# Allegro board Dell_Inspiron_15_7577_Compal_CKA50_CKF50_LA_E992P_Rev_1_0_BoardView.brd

Outline 383.3 x 146.9 mm; copper layers: TOP, GND1, IN1, GND2, IN2, VCC, IN3, IN4, GND3, IN5, GND4, BOTTOM. Coordinates in mm from the lower left corner of the outline.

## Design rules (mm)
constraint set DEFAULT: min track width 0.14
net group 18/15: nets H_THERMTRIP# H_THERMTRIP#_R
net group ASYNCHRONOUS: nets H_PROCHOT# PROCHOT
net group CLK_PCIE_N5: nets CLK_PCIE_N5 CLK_PCIE_P5
net group CPU_DDI3_N0: nets CPU_DDI3_N0 CPU_DDI3_P0
net group CPU_DDI3_N1: nets CPU_DDI3_N1 CPU_DDI3_P1
net group CRT: nets CRT_DDCCLK_CON CRT_DDCDATA_CON
net group DDC_SCL_HDMI: nets DDC_SCL_HDMI DDC_SDA_HDMI
net group DDI3_AUXN: nets DDI3_AUXN DDI3_AUXP
net group DDI3_AUXN_C: nets DDI3_AUXN_C DDI3_AUXP_C
net group DDR_A_CLK0: nets DDR_A_CLK0 DDR_A_CLK#0
net group DDR_A_CLK1: nets DDR_A_CLK1 DDR_A_CLK#1
net group DDR_ALERT: nets DDR_A_ALERT# DDR_B_ALERT#
net group DDR_B_CLK0: nets DDR_B_CLK0 DDR_B_CLK#0
net group DDR_B_CLK1: nets DDR_B_CLK1 DDR_B_CLK#1
net group DDR_RESET: nets DDR4_DRAMRST# H_DRAMRST#
net group DIFFPAIR1: nets CLK_SMB DAT_SMB
net group DMIC_CLK: nets DMIC_CLK DMIC_DAT
net group DMIC_CLK_R: nets DMIC_CLK_R DMIC_DATA_R
net group DP6: nets ISUMN_SA ISUMP_SA
net group DP_N0: nets DP_N0 DP_P0
net group DP_N1: nets DP_N1 DP_P1
net group IFPC_CLK_CN: nets IFPC_CLK_CN IFPC_CLK_CP
net group IFPC_CLK_N: nets IFPC_CLK_N IFPC_CLK_P
net group IFPC_TX0_CN: nets IFPC_TX0_CN IFPC_TX0_CP
net group IFPC_TX0_N: nets IFPC_TX0_N IFPC_TX0_P
net group IFPC_TX1_CN: nets IFPC_TX1_CN IFPC_TX1_CP
net group IFPC_TX1_N: nets IFPC_TX1_N IFPC_TX1_P
net group IFPC_TX2_CN: nets IFPC_TX2_CN IFPC_TX2_CP
net group IFPC_TX2_N: nets IFPC_TX2_N IFPC_TX2_P
net group PCIE_PRX_TBTTX_N1: nets PCIE_PRX_TBTTX_N1 PCIE_PRX_TBTTX_P1
net group PCIE_PRX_TBTTX_N1_C: nets PCIE_PRX_TBTTX_N1_C PCIE_PRX_TBTTX_P1_C
net group PCIE_PRX_TBTTX_N2: nets PCIE_PRX_TBTTX_N2 PCIE_PRX_TBTTX_P2
net group PCIE_PRX_TBTTX_N2_C: nets PCIE_PRX_TBTTX_N2_C PCIE_PRX_TBTTX_P2_C
net group PCIE_PRX_TBTTX_N3: nets PCIE_PRX_TBTTX_N3 PCIE_PRX_TBTTX_P3
net group PCIE_PRX_TBTTX_N3_C: nets PCIE_PRX_TBTTX_N3_C PCIE_PRX_TBTTX_P3_C
net group PCIE_PRX_TBTTX_N4: nets PCIE_PRX_TBTTX_N4 PCIE_PRX_TBTTX_P4
net group PCIE_PRX_TBTTX_N4_C: nets PCIE_PRX_TBTTX_N4_C PCIE_PRX_TBTTX_P4_C
net group PCIE_PTX_LANRX_N5: nets PCIE_PTX_LANRX_N5 PCIE_PTX_LANRX_N5_C
net group PCIE_PTX_LANRX_P5: nets PCIE_PTX_LANRX_P5 PCIE_PTX_LANRX_P5_C
net group PCIE_PTX_TBTRX_N1: nets PCIE_PTX_TBTRX_N1 PCIE_PTX_TBTRX_P1
net group PCIE_PTX_TBTRX_N1_C: nets PCIE_PTX_TBTRX_N1_C PCIE_PTX_TBTRX_P1_C
net group PCIE_PTX_TBTRX_N2: nets PCIE_PTX_TBTRX_N2 PCIE_PTX_TBTRX_P2
net group PCIE_PTX_TBTRX_N2_C: nets PCIE_PTX_TBTRX_N2_C PCIE_PTX_TBTRX_P2_C
net group PCIE_PTX_TBTRX_N3: nets PCIE_PTX_TBTRX_N3 PCIE_PTX_TBTRX_P3
net group PCIE_PTX_TBTRX_N3_C: nets PCIE_PTX_TBTRX_N3_C PCIE_PTX_TBTRX_P3_C
net group PCIE_PTX_TBTRX_N4: nets PCIE_PTX_TBTRX_N4 PCIE_PTX_TBTRX_P4
net group PCIE_PTX_TBTRX_N4_C: nets PCIE_PTX_TBTRX_N4_C PCIE_PTX_TBTRX_P4_C
net group PLATFORM_RESET: nets TBT_RESET_N_EC# USB_EN#
net group TBT_A_AUX_N: nets TBT_A_AUX_N TBT_A_AUX_P
net group TBT_A_AUX_N_C: nets TBT_A_AUX_N_C TBT_A_AUX_P_C
net group TBT_A_USB20_L_NB: nets TBT_A_USB20_L_NB TBT_A_USB20_L_PB
net group TBT_A_USB20_L_NT: nets TBT_A_USB20_L_NT TBT_A_USB20_L_PT
net group TBT_A_USB20_N: nets TBT_A_USB20_N TBT_A_USB20_P
net group TBT_A_USB20_NB: nets TBT_A_USB20_NB TBT_A_USB20_PB
net group TBT_A_USB20_NT: nets TBT_A_USB20_NT TBT_A_USB20_PT
net group TBTA_SBU: nets TBTA_SBU1 TBTA_SBU2
net group TMDS_T_TX0N_R: nets TMDS_T_TX0N_R TMDS_T_TX0P_R
net group TMDS_T_TX1N_R: nets TMDS_T_TX1N_R TMDS_T_TX1P_R
net group TMDS_T_TX2N_R: nets TMDS_T_TX2N_R TMDS_T_TX2P_R
net group TMDS_T_TXCN_R: nets TMDS_T_TXCN_R TMDS_T_TXCP_R
net group UP2: nets +1.2V_RTM N10178
net group USB3_A_TTX_DRX_N0: nets USB3_A_TTX_DRX_N0 USB3_A_TTX_DRX_P0
net group USB3_A_TTX_DRX_N1: nets USB3_A_TTX_DRX_N1 USB3_A_TTX_DRX_P1
net group USB3RN1_C: nets USB3RN1_C USB3RP1_C
net group USB3RN1_RE: nets USB3RN1_RE USB3RP1_RE
net group USB3TN1_C: nets USB3TN1_C USB3TP1_C
net group USB3TN1_RE: nets USB3TN1_RE USB3TP1_RE
net group USB3TN1_RE_C: nets USB3TN1_RE_C USB3TP1_RE_C
net group USB3TN2_C: nets USB3TN2_C USB3TP2_C
net group USB3TN3_C: nets USB3TN3_C USB3TP3_C
net group USB20_N2_L: nets USB20_N2_L USB20_P2_L
net group USB20_N3_L: nets USB20_N3_L USB20_P3_L
net group USB20_N8: nets USB20_N8 USB20_P8
net group USB20_N8_R: nets USB20_N8_R USB20_P8_R
net group 5: nets KSI0 KSI1 KSI2 KSI3 KSI4 KSI5 KSI6 KSI7 KSO0 KSO1 KSO2 KSO3 KSO4 KSO5 KSO6 KSO7 KSO8 KSO9 KSO10 KSO11 KSO12 KSO13 KSO14 KSO15 KSO16
net group 10: nets AUD_HP1_JACK_L AUD_HP1_JACK_L1 AUD_HP1_JACK_R AUD_HP1_JACK_R1 AUD_PORTA_L_R_B AUD_PORTA_R_R_B AUD_SPK_L+ AUD_SPK_L+_C AUD_SPK_L- AUD_SPK_L-_C AUD_SPK_R+ AUD_SPK_R+_C AUD_SPK_R- AUD_SPK_R-_C BAT1_LED# BAT2_LED# BREATH_LED# BREATH_LED_MB BREATH_LED_R2 CAP_LED CAP_LED_R KB_BL_DET KB_LED_PWM KB_LED_PWM# LED1 LED2 LINE1_VREFO_L LINE1_VREFO_R MIC2_VREFO PCH_SATA_LED# REMOTE1+ REMOTE1- REMOTE2+ REMOTE2- SATA_LED_EN SSD_LED#
net group 12: nets ALL_SYS_PWRGD CPU_TRIGGER CPU_TRIGGER_R H_CATERR# H_CPUPWRGD H_PM_DOWN H_PM_DOWN_R H_PM_SYNC_R H_PROCHOT#_R H_VCCST_PWRGD PCH_PLTRST# PCH_PLTRST#_EC PCH_TRIGGER PCH_TRIGGER_R PLTRST_CPU# RUNPWROK TBT_RST#_R VCCST_PWRGD_CPU XDP_PLTRST# XDP_PWRGOOD
net group 12/15: nets SD_CLK SD_CLK_R SD_CMD SD_D0 SD_D1 SD_D2 SD_D3
net group 15: nets AC_PRESENT ACAV_IN MEC_XTAL1 MEC_XTAL1_R MEC_XTAL2 PCH_DPWROK PCH_RSMRST# PCH_RSMRST#_R PCH_RTCRST# PCH_RTCX1 PCH_RTCX2 PCH_SRTCRST# RESET_N SUSCLK SUSCLK_R SYS_RESET# TBT_RESET_N TBT_XTAL_25_IN TBT_XTAL_25_IN_R TBT_XTAL_25_OUT TBT_XTAL_25_OUT_R TBTA_MRESET XDP_DBRESET# XTLI XTLO
net group 15/12: nets VR_SVID_ALERT# VR_SVID_ALERT#_R VR_SVID_CLK VR_SVID_DATA
net group 18/12: nets H_PECI PECI PECI_EC PECI_EC_R
net group 25: nets USB2_VBUSSENSE VCCIO_SENSE VSSIO_SENSE
net group AUDIO: nets LINE1-L_C LINE1-L_R LINE1_L LINE1_R
net group DDRCMD_4/12_16: nets DDR_A_ACT# DDR_A_BG0 DDR_A_BG1 DDR_A_BS0 DDR_A_BS1 DDR_A_CAS# DDR_A_CKE0 DDR_A_CKE1 DDR_A_CS#0 DDR_A_CS#1 DDR_A_MA0 DDR_A_MA1 DDR_A_MA2 DDR_A_MA3 DDR_A_MA4 DDR_A_MA5 DDR_A_MA6 DDR_A_MA7 DDR_A_MA8 DDR_A_MA9 DDR_A_MA10 DDR_A_MA11 DDR_A_MA12 DDR_A_MA13 DDR_A_ODT0 DDR_A_ODT1 DDR_A_PAR DDR_A_RAS# DDR_A_WE# DDR_B_ACT# DDR_B_BG0 DDR_B_BG1 DDR_B_BS0 DDR_B_BS1 DDR_B_CAS# DDR_B_CKE0 DDR_B_CKE1 DDR_B_CS#0 DDR_B_CS#1 DDR_B_MA0 DDR_B_MA1 DDR_B_MA2 DDR_B_MA3 DDR_B_MA4 DDR_B_MA5 DDR_B_MA6 DDR_B_MA7 DDR_B_MA8 DDR_B_MA9 DDR_B_MA10 DDR_B_MA11 DDR_B_MA12 DDR_B_MA13 DDR_B_ODT0 DDR_B_ODT1 DDR_B_PAR DDR_B_RAS# DDR_B_WE#
net group DDRD0_4/8_25: nets DDR_A_D0 DDR_A_D1 DDR_A_D2 DDR_A_D3 DDR_A_D4 DDR_A_D5 DDR_A_D6 DDR_A_D7 DDR_A_D16 DDR_A_D17 DDR_A_D18 DDR_A_D19 DDR_A_D20 DDR_A_D21 DDR_A_D22 DDR_A_D23 DDR_A_D32 DDR_A_D33 DDR_A_D34 DDR_A_D35 DDR_A_D36 DDR_A_D37 DDR_A_D38 DDR_A_D39 DDR_A_D48 DDR_A_D49 DDR_A_D50 DDR_A_D51 DDR_A_D52 DDR_A_D53 DDR_A_D54 DDR_A_D55 DDR_B_D0 DDR_B_D1 DDR_B_D2 DDR_B_D3 DDR_B_D4 DDR_B_D5 DDR_B_D6 DDR_B_D7 DDR_B_D16 DDR_B_D17 DDR_B_D18 DDR_B_D19 DDR_B_D20 DDR_B_D21 DDR_B_D22 DDR_B_D23 DDR_B_D32 DDR_B_D33 DDR_B_D34 DDR_B_D35 DDR_B_D36 DDR_B_D37 DDR_B_D38 DDR_B_D39 DDR_B_D48 DDR_B_D49 DDR_B_D50 DDR_B_D51 DDR_B_D52 DDR_B_D53 DDR_B_D54 DDR_B_D55
net group DDRD1_4/8_25: nets DDR_A_D8 DDR_A_D9 DDR_A_D10 DDR_A_D11 DDR_A_D12 DDR_A_D13 DDR_A_D14 DDR_A_D15 DDR_A_D24 DDR_A_D25 DDR_A_D26 DDR_A_D27 DDR_A_D28 DDR_A_D29 DDR_A_D30 DDR_A_D31 DDR_A_D40 DDR_A_D41 DDR_A_D42 DDR_A_D43 DDR_A_D44 DDR_A_D45 DDR_A_D46 DDR_A_D47 DDR_A_D56 DDR_A_D57 DDR_A_D58 DDR_A_D59 DDR_A_D60 DDR_A_D61 DDR_A_D62 DDR_A_D63 DDR_B_D8 DDR_B_D9 DDR_B_D10 DDR_B_D11 DDR_B_D12 DDR_B_D13 DDR_B_D14 DDR_B_D15 DDR_B_D24 DDR_B_D25 DDR_B_D26 DDR_B_D27 DDR_B_D28 DDR_B_D29 DDR_B_D30 DDR_B_D31 DDR_B_D40 DDR_B_D41 DDR_B_D42 DDR_B_D43 DDR_B_D44 DDR_B_D45 DDR_B_D46 DDR_B_D47 DDR_B_D56 DDR_B_D57 DDR_B_D58 DDR_B_D59 DDR_B_D60 DDR_B_D61 DDR_B_D62 DDR_B_D63
net group DDRDQS_25: nets DDR_A_DQS0 DDR_A_DQS1 DDR_A_DQS2 DDR_A_DQS3 DDR_A_DQS4 DDR_A_DQS5 DDR_A_DQS6 DDR_A_DQS7 DDR_A_DQS#0 DDR_A_DQS#1 DDR_A_DQS#2 DDR_A_DQS#3 DDR_A_DQS#4 DDR_A_DQS#5 DDR_A_DQS#6 DDR_A_DQS#7 DDR_B_DQS0 DDR_B_DQS1 DDR_B_DQS2 DDR_B_DQS3 DDR_B_DQS4 DDR_B_DQS5 DDR_B_DQS6 DDR_B_DQS7 DDR_B_DQS#0 DDR_B_DQS#1 DDR_B_DQS#2 DDR_B_DQS#3 DDR_B_DQS#4 DDR_B_DQS#5 DDR_B_DQS#6 DDR_B_DQS#7
net group DMI: nets DMI_CRX_PTX_N0 DMI_CRX_PTX_N1 DMI_CRX_PTX_N2 DMI_CRX_PTX_N3 DMI_CRX_PTX_P0 DMI_CRX_PTX_P1 DMI_CRX_PTX_P2 DMI_CRX_PTX_P3 DMI_CTX_PRX_N0 DMI_CTX_PRX_N1 DMI_CTX_PRX_N2 DMI_CTX_PRX_N3 DMI_CTX_PRX_P0 DMI_CTX_PRX_P1 DMI_CTX_PRX_P2 DMI_CTX_PRX_P3
net group DP_12_15: nets CRT_B CRT_G CRT_HSYNC_CON CRT_R CRT_VSYNC_CON DP_CRT_B DP_CRT_G DP_CRT_HSYNC_CON DP_CRT_R DP_CRT_VSYNC_CON
net group EDP_12_15: nets EDP_AUXN EDP_AUXN_C EDP_AUXP EDP_AUXP_C EDP_TXN0 EDP_TXN0_C EDP_TXN1 EDP_TXN1_C EDP_TXN2 EDP_TXN2_C EDP_TXN3 EDP_TXN3_C EDP_TXP0 EDP_TXP0_C EDP_TXP1 EDP_TXP1_C EDP_TXP2 EDP_TXP2_C EDP_TXP3 EDP_TXP3_C
net group ESPI_5_15: nets ESPI_CLK ESPI_CS# ESPI_IO0 ESPI_IO1 ESPI_IO2 ESPI_IO3 ESPI_RESET# PCH_ESPI_CLK PCH_ESPI_IO0 PCH_ESPI_IO1 PCH_ESPI_IO2 PCH_ESPI_IO3
net group FBA_DBI: nets FBA_DBI0 FBA_DBI1 FBA_DBI2 FBA_DBI3 FBA_DBI4 FBA_DBI5 FBA_DBI6 FBA_DBI7
net group GDDR5_CLK_13.5/12_20: nets FBB_CLK0 FBB_CLK0# FBB_CLK1 FBB_CLK1#
net group GDDR5_CMD_13.5/12_20: nets FBA_CMD0 FBA_CMD1 FBA_CMD2 FBA_CMD3 FBA_CMD4 FBA_CMD5 FBA_CMD6 FBA_CMD7 FBA_CMD8 FBA_CMD9 FBA_CMD10 FBA_CMD11 FBA_CMD12 FBA_CMD13 FBA_CMD14 FBA_CMD15 FBA_CMD16 FBA_CMD17 FBA_CMD18 FBA_CMD19 FBA_CMD20 FBA_CMD21 FBA_CMD22 FBA_CMD23 FBA_CMD24 FBA_CMD25 FBA_CMD26 FBA_CMD27 FBA_CMD28 FBA_CMD29 FBA_CMD30 FBA_CMD31 FBB_CMD0 FBB_CMD1 FBB_CMD2 FBB_CMD3 FBB_CMD4 FBB_CMD5 FBB_CMD6 FBB_CMD7 FBB_CMD8 FBB_CMD9 FBB_CMD10 FBB_CMD11 FBB_CMD12 FBB_CMD13 FBB_CMD14 FBB_CMD15 FBB_CMD16 FBB_CMD17 FBB_CMD18 FBB_CMD19 FBB_CMD20 FBB_CMD21 FBB_CMD22 FBB_CMD23 FBB_CMD24 FBB_CMD25 FBB_CMD26 FBB_CMD27 FBB_CMD28 FBB_CMD29 FBB_CMD30 FBB_CMD31 FBC_CMD0 FBC_CMD1 FBC_CMD2 FBC_CMD3 FBC_CMD4 FBC_CMD5 FBC_CMD6 FBC_CMD7 FBC_CMD8 FBC_CMD9 FBC_CMD10 FBC_CMD11 FBC_CMD12 FBC_CMD13 FBC_CMD14 FBC_CMD15 FBC_CMD16 FBC_CMD17 FBC_CMD18 FBC_CMD19 FBC_CMD20 FBC_CMD21 FBC_CMD22 FBC_CMD23 FBC_CMD24 FBC_CMD25 FBC_CMD26 FBC_CMD27 FBC_CMD28 FBC_CMD29 FBC_CMD30 FBC_CMD31
net group GDDR5_DATA/DBI/EDC_13.5/16/18_20: nets FBB_D0 FBB_D1 FBB_D2 FBB_D3 FBB_D4 FBB_D5 FBB_D6 FBB_D7 FBB_D8 FBB_D9 FBB_D10 FBB_D11 FBB_D12 FBB_D13 FBB_D14 FBB_D15 FBB_D16 FBB_D17 FBB_D18 FBB_D19 FBB_D20 FBB_D21 FBB_D22 FBB_D23 FBB_D24 FBB_D25 FBB_D26 FBB_D27 FBB_D28 FBB_D29 FBB_D30 FBB_D31 FBB_D32 FBB_D33 FBB_D34 FBB_D35 FBB_D36 FBB_D37 FBB_D38 FBB_D39 FBB_D40 FBB_D41 FBB_D42 FBB_D43 FBB_D44 FBB_D45 FBB_D46 FBB_D47 FBB_D48 FBB_D49 FBB_D50 FBB_D51 FBB_D52 FBB_D53 FBB_D54 FBB_D55 FBB_D56 FBB_D57 FBB_D58 FBB_D59 FBB_D60 FBB_D61 FBB_D62 FBB_D63 FBB_DBI0 FBB_DBI1 FBB_DBI2 FBB_DBI3 FBB_DBI4 FBB_DBI5 FBB_DBI6 FBB_DBI7 FBB_EDC0 FBB_EDC1 FBB_EDC2 FBB_EDC3 FBB_EDC4 FBB_EDC5 FBB_EDC6 FBB_EDC7 FBC_DBI0 FBC_DBI1 FBC_DBI2 FBC_DBI3 FBC_DBI4 FBC_DBI5 FBC_DBI6 FBC_DBI7
net group GDDR5_WCLK_10.8/16/18_20: nets FBA_WCK01 FBA_WCK01# FBA_WCK23 FBA_WCK23# FBA_WCK45 FBA_WCK45# FBA_WCK67 FBA_WCK67# FBB_WCK01 FBB_WCK01# FBB_WCK23 FBB_WCK23# FBB_WCK45 FBB_WCK45# FBB_WCK67 FBB_WCK67# FBC_WCK01 FBC_WCK01# FBC_WCK23 FBC_WCK23# FBC_WCK45 FBC_WCK45# FBC_WCK67 FBC_WCK67#
net group GND: nets AUD_AGND
net group HDA: nets HDA_BITCLK_AUDIO
net group HDA_5_15: nets AUD_AZA_CPU_SCLK AUD_AZA_CPU_SCLK_R AUD_AZA_CPU_SDI AUD_AZA_CPU_SDI_R AUD_AZA_CPU_SDO AUD_AZA_CPU_SDO_R HDA_BITCLK HDA_CODEC_SDIN0 HDA_SDIN0_AUDIO HDA_SDOUT HDA_SDOUT_AUDIO HDA_SYNC HDA_SYNC_AUDIO
net group HDMI: nets IFPC_I2C_8409_CLK IFPC_I2C_8409_DAT IFPC_I2C_CLK IFPC_I2C_CLK_R IFPC_I2C_DAT IFPC_I2C_DAT_R
net group HDMI_12_20: nets TMDS_T_TX0N TMDS_T_TX0P TMDS_T_TX1N TMDS_T_TX1P TMDS_T_TX2N TMDS_T_TX2P TMDS_T_TXCN TMDS_T_TXCP
net group I2C_5_15: nets CLK_TP_SIO DAT_TP_SIO I2C1_SCK_TP I2C1_SCK_TP_C I2C1_SDA_TP I2C1_SDA_TP_C
net group LAN_30: nets MDI0+ MDI0- MDI1+ MDI1- MDI2+ MDI2- MDI3+ MDI3- MDO0+ MDO0- MDO1+ MDO1- MDO2+ MDO2- MDO3+ MDO3-
net group LED: nets MASK_SATA_LED#
net group PCIE_12: nets PCIE_PRX_SSDTX_N10 PCIE_PRX_SSDTX_N11 PCIE_PRX_SSDTX_N12 PCIE_PRX_SSDTX_P10 PCIE_PRX_SSDTX_P11 PCIE_PRX_SSDTX_P12 PCIE_PRX_WLANTX_N6 PCIE_PRX_WLANTX_P6 PCIE_PTX_SSDRX_N10 PCIE_PTX_SSDRX_N10_C PCIE_PTX_SSDRX_N11 PCIE_PTX_SSDRX_N11_C PCIE_PTX_SSDRX_N12 PCIE_PTX_SSDRX_N12_C PCIE_PTX_SSDRX_P10 PCIE_PTX_SSDRX_P10_C PCIE_PTX_SSDRX_P11 PCIE_PTX_SSDRX_P11_C PCIE_PTX_SSDRX_P12 PCIE_PTX_SSDRX_P12_C PCIE_PTX_WLANRX_N6 PCIE_PTX_WLANRX_P6 PCIE_PTX_WLANRX_RE_N6 PCIE_PTX_WLANRX_RE_P6 SATA_PRX_SSDTX_N0A SATA_PRX_SSDTX_P0A SATA_PTX_SSDRX_N0A SATA_PTX_SSDRX_N0A_C SATA_PTX_SSDRX_P0A SATA_PTX_SSDRX_P0A_C
net group PCIE_LAN: nets PCIE_PRX_LANTX_N5 PCIE_PRX_LANTX_N5_C PCIE_PRX_LANTX_P5 PCIE_PRX_LANTX_P5_C
net group PCIE_WLAN: nets CPU_DDI1_N0 CPU_DDI1_N1 CPU_DDI1_N2 CPU_DDI1_N3 CPU_DDI1_P0 CPU_DDI1_P1 CPU_DDI1_P2 CPU_DDI1_P3 CPU_DDI2_N0 CPU_DDI2_N1 CPU_DDI2_N2 CPU_DDI2_N3 CPU_DDI2_P0 CPU_DDI2_P1 CPU_DDI2_P2 CPU_DDI2_P3 CPU_DP1_AUXN_C CPU_DP1_AUXP_C CPU_DP1_N0_C CPU_DP1_N1_C CPU_DP1_N2_C CPU_DP1_N3_C CPU_DP1_P0_C CPU_DP1_P1_C CPU_DP1_P2_C CPU_DP1_P3_C CPU_DP2_AUXN_C CPU_DP2_AUXP_C CPU_DP2_N0_C CPU_DP2_N1_C CPU_DP2_N2_C CPU_DP2_N3_C CPU_DP2_P0_C CPU_DP2_P1_C CPU_DP2_P2_C CPU_DP2_P3_C DDI1_AUXN DDI1_AUXP DDI2_AUXN DDI2_AUXP
net group PEG_12_15: nets PEG_GTX_C_HRX_N0 PEG_GTX_C_HRX_N1 PEG_GTX_C_HRX_N2 PEG_GTX_C_HRX_N3 PEG_GTX_C_HRX_N4 PEG_GTX_C_HRX_N5 PEG_GTX_C_HRX_N6 PEG_GTX_C_HRX_N7 PEG_GTX_C_HRX_N8 PEG_GTX_C_HRX_N9 PEG_GTX_C_HRX_N10 PEG_GTX_C_HRX_N11 PEG_GTX_C_HRX_N12 PEG_GTX_C_HRX_N13 PEG_GTX_C_HRX_N14 PEG_GTX_C_HRX_N15 PEG_GTX_C_HRX_P0 PEG_GTX_C_HRX_P1 PEG_GTX_C_HRX_P2 PEG_GTX_C_HRX_P3 PEG_GTX_C_HRX_P4 PEG_GTX_C_HRX_P5 PEG_GTX_C_HRX_P6 PEG_GTX_C_HRX_P7 PEG_GTX_C_HRX_P8 PEG_GTX_C_HRX_P9 PEG_GTX_C_HRX_P10 PEG_GTX_C_HRX_P11 PEG_GTX_C_HRX_P12 PEG_GTX_C_HRX_P13 PEG_GTX_C_HRX_P14 PEG_GTX_C_HRX_P15 PEG_GTX_HRX_N0 PEG_GTX_HRX_N1 PEG_GTX_HRX_N2 PEG_GTX_HRX_N3 PEG_GTX_HRX_N4 PEG_GTX_HRX_N5 PEG_GTX_HRX_N6 PEG_GTX_HRX_N7 PEG_GTX_HRX_N8 PEG_GTX_HRX_N9 PEG_GTX_HRX_N10 PEG_GTX_HRX_N11 PEG_GTX_HRX_N12 PEG_GTX_HRX_N13 PEG_GTX_HRX_N14 PEG_GTX_HRX_N15 PEG_GTX_HRX_P0 PEG_GTX_HRX_P1 PEG_GTX_HRX_P2 PEG_GTX_HRX_P3 PEG_GTX_HRX_P4 PEG_GTX_HRX_P5 PEG_GTX_HRX_P6 PEG_GTX_HRX_P7 PEG_GTX_HRX_P8 PEG_GTX_HRX_P9 PEG_GTX_HRX_P10 PEG_GTX_HRX_P11 PEG_GTX_HRX_P12 PEG_GTX_HRX_P13 PEG_GTX_HRX_P14 PEG_GTX_HRX_P15 PEG_HTX_C_GRX_N0 PEG_HTX_C_GRX_N1 PEG_HTX_C_GRX_N2 PEG_HTX_C_GRX_N3 PEG_HTX_C_GRX_N4 PEG_HTX_C_GRX_N5 PEG_HTX_C_GRX_N6 PEG_HTX_C_GRX_N7 PEG_HTX_C_GRX_N8 PEG_HTX_C_GRX_N9 PEG_HTX_C_GRX_N10 PEG_HTX_C_GRX_N11 PEG_HTX_C_GRX_N12 PEG_HTX_C_GRX_N13 PEG_HTX_C_GRX_N14 PEG_HTX_C_GRX_N15 PEG_HTX_C_GRX_P0 PEG_HTX_C_GRX_P1 PEG_HTX_C_GRX_P2 PEG_HTX_C_GRX_P3 PEG_HTX_C_GRX_P4 PEG_HTX_C_GRX_P5 PEG_HTX_C_GRX_P6 PEG_HTX_C_GRX_P7 PEG_HTX_C_GRX_P8 PEG_HTX_C_GRX_P9 PEG_HTX_C_GRX_P10 PEG_HTX_C_GRX_P11 PEG_HTX_C_GRX_P12 PEG_HTX_C_GRX_P13 PEG_HTX_C_GRX_P14 PEG_HTX_C_GRX_P15 PEG_HTX_GRX_N0 PEG_HTX_GRX_N1 PEG_HTX_GRX_N2 PEG_HTX_GRX_N3 PEG_HTX_GRX_N4 PEG_HTX_GRX_N5 PEG_HTX_GRX_N6 PEG_HTX_GRX_N7 PEG_HTX_GRX_N8 PEG_HTX_GRX_N9 PEG_HTX_GRX_N10 PEG_HTX_GRX_N11 PEG_HTX_GRX_N12 PEG_HTX_GRX_N13 PEG_HTX_GRX_N14 PEG_HTX_GRX_N15 PEG_HTX_GRX_P0 PEG_HTX_GRX_P1 PEG_HTX_GRX_P2 PEG_HTX_GRX_P3 PEG_HTX_GRX_P4 PEG_HTX_GRX_P5 PEG_HTX_GRX_P6 PEG_HTX_GRX_P7 PEG_HTX_GRX_P8 PEG_HTX_GRX_P9 PEG_HTX_GRX_P10 PEG_HTX_GRX_P11 PEG_HTX_GRX_P12 PEG_HTX_GRX_P13 PEG_HTX_GRX_P14 PEG_HTX_GRX_P15
net group PLATFORM RESET: nets HW_ACAV_IN
net group PLATFORM_15_20: nets CLK_PCIE_SSD CLK_PCIE_SSD# CLK_PCIE_WLAN CLK_PCIE_WLAN# CPU_24MHZ_N CPU_24MHZ_P PCH_CPU_BCLK_N PCH_CPU_BCLK_P PCH_CPU_PCIBCLK_N PCH_CPU_PCIBCLK_P PCH_XDP_CLK_N PCH_XDP_CLK_P
net group PLATFORM_CLK: nets CLK_PCIE_LAN CLK_PCIE_LAN# CLK_PEG_GPU CLK_PEG_GPU#
net group PWN: nets +VCCSTG
net group SATA_12_15/12: nets SATA_PRX_DTX_N1B SATA_PRX_DTX_N1B_RC SATA_PRX_DTX_P1B SATA_PRX_DTX_P1B_RC SATA_PTX_DRX_N1B SATA_PTX_DRX_N1B_RC SATA_PTX_DRX_P1B SATA_PTX_DRX_P1B_RC
net group SENSE: nets VCCGT_SENSE VCCSA_SENSE VCCSENSE VSSGT_SENSE VSSSA_SENSE VSSSENSE
net group SENSING: nets CSSN_B+ CSSN_NVVDD CSSP_B+ CSSP_NVVDD VIN1N VIN1P VIN2N VIN2P
net group SMBUS_5_15: nets GPU_THM_SMBCLK GPU_THM_SMBDAT PCH_SMBCLK PCH_SMBDATA SMBCLK SMBDATA SML0_SMBCLK SML0_SMBDATA THM_SML1_CLK THM_SML1_DATA VGA_SMB_CK2 VGA_SMB_DA2
net group SPI: nets PCH_SPI_CLK_R1
net group SPI_5_20: nets PCH_SPI1_CLK_R PCH_SPI_CLK PCH_SPI_CLK_R PCH_SPI_CS2# PCH_SPI_CS2#_R PCH_SPI_CS# PCH_SPI_CS#_R PCH_SPI_HOLD# PCH_SPI_HOLD#_R PCH_SPI_MISO PCH_SPI_MOSI PCH_SPI_SI PCH_SPI_SI_R PCH_SPI_SO PCH_SPI_SO_R PCH_SPI_WP# PCH_SPI_WP#_R
net group SRC: nets LAN_CLKREQ# SSD_CLK_REQ# VGA_CLK_REQ# WLAN_CLK_REQ#
net group SRC_15_20/15: nets PEX_CLKREQ# TBT_CLK_REQ# TBT_CLK_REQ#_R
net group TBT16: nets USB3_A_TRX_DTX_N0 USB3_A_TRX_DTX_N1 USB3_A_TRX_DTX_P0 USB3_A_TRX_DTX_P1 USB3_A_TTX_C_DRX_N0 USB3_A_TTX_C_DRX_N1 USB3_A_TTX_C_DRX_P0 USB3_A_TTX_C_DRX_P1
net group USB20: nets USBP1_D+ USBP1_D+_R USBP1_D- USBP1_D-_R
net group USB20_12: nets USB20_N1 USB20_N2 USB20_N3 USB20_N4 USB20_N7 USB20_N9 USB20_N9_R USB20_N12 USB20_N12_R USB20_P1 USB20_P2 USB20_P3 USB20_P4 USB20_P7 USB20_P9 USB20_P9_R USB20_P12 USB20_P12_R
net group USB30_12: nets USB3RN1 USB3RN2 USB3RN3 USB3RP1 USB3RP2 USB3RP3 USB3TN1 USB3TN2 USB3TN3 USB3TP1 USB3TP2 USB3TP3
net group UT1: nets +3.3V_FLASH TBT_I2C_SCL TBT_I2C_SDA TBTA_I2C_INT TBTA_LSTX
net group UT4: nets N135625951 TBTA_CC1 TBTA_CC2
nets with their own width: min track width 0.254; nets N18094850 NVVDD_VSS_SENSE VREF_CPU
nets with their own width: min track width 0.508; nets 5VS_FAN2 +0.9V_CIO +0.9V_DP +0.9V_LVR_OUT +0.9V_PCIE +0.9V_SVR +0.9V_USB +1.2V_VCCPLL_OC +1.8V_AVDD +1.8V_DVDD +1.8V_PRIM +1.8VALW_EC +1V_APLLEBB +1V_MPHY_MPHYPLL +1V_PCH +1V_PCH_AZPLL +1V_PCH_CLK5 +1V_PCH_USBPLL +1V_VCCDSW +3.3V_ANA_PCIE +3.3V_ANA_USB2 +3.3V_LC +3.3V_TBT_SX +3V_DVDD +3V_FPSW +3V_HDA +3V_PCH_AZIO +3V_PCH_DSW +3V_PCH_SPI +3V_RTM +3V_TPM +3V_USBRD +3VALW +3VALW_EC +3VALW_PD +3VLP +3VS +3VS_CAM +3VS_TP +3VS_TP_OUT +5VS +5VS_KBL +5VS_TS +CHGRTC +DEBUG_PWR +INV_PWR_SRC +LAN_IO +LAN_VDD +RTCBATT +RTCVCC +V_DDR_REFA +V_DDR_REFA_R +V_DDR_REFB +V_DDR_REFB_R +VCCIO +VCCST +VCCST_OUT +VCCSTG_OUT AVCC33 DDR_RCOMP0 DDR_RCOMP1 DDR_RCOMP2 GND N131311358 NVVDD_B+ PEG_RCOMP TBT_SVR_IND VDD_DAC_33
nets with their own width: min track width 0.635; nets +5VALW
nets with their own width: min track width 1.016; nets +1.2V_VCCPLL_OC_OUT +2.5V_MEM +3.3V_TBT_S0 +3VS_CR +3VS_WLAN +5VS_HDD +5VS_OUT +CRT_5V_OUT +VCC_3IN1 +VDISPLAY_VCC
nets with their own width: min track width 1.27; nets +PEX_VDD
nets with their own width: min track width 1.524; nets +0.6VS +5V_AVDD +5V_PVDD +TBTA_VBUS
nets with their own width: min track width 1.651; nets +1V8_AON +1V8_MAIN +FBX_PLLAVDD
nets with their own width: min track width 2.032; nets +5V_CHGUSB_1 +EDPVDD +EDPVDD_OUT
nets with their own width: min track width 2.54; nets +5V_CHGUSB_3
nets with their own width: min track width 3.048; nets +3.3VDX_SSD
nets with their own width: min track width 3.81; nets +1V_MPHY

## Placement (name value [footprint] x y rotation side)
C5235  1U_0402_10V6K  [C_0402]  226.42 26.27 90 bottom
CA1  4.7U_0603_6.3V6K  [C_0603]  351.26 26.32 270 top
CA2  0.1U_0402_10V6K  [C_0402]  346.61 25.48 90 top
CA3  0.1U_0402_10V6K  [C_0402]  335.43 23.84 0 top
CA4  1U_0402_6.3V6K  [C_0402]  336.4 7.71 180 bottom
CA7  1U_0402_6.3V6K  [C_0402]  331.98 8.27 270 top
CA8  4.7U_0603_6.3V6K  [C_0603]  338.8 16.13 180 top
CA9  0.1U_0402_10V6K  [C_0402]  338.57 17.24 180 top
CA10  0.22U_0603_25V7K  [C_0603]  337.1 12.47 270 top
CA11  10U_0603_6.3V6M~D  [C_0603]  339.32 27.59 90 top
CA12  0.1U_0402_10V6K  [C_0402]  344.46 23.85 270 bottom
CA13  10U_0603_6.3V6M~D  [C_0603]  340.53 27.59 90 top
CA14  0.1U_0402_10V6K  [C_0402]  341.61 27.64 90 top
CA15  1U_0603_10V6K  [C_0603]  351.38 20.98 180 top
CA16  2.2U_0402_6.3V6M  [C_0402]  350.83 19.52 180 top
CA17  0.1U_0402_10V6K  [C_0402]  348.84 16.32 270 top
CA18  4.7U_0603_6.3V6K  [C_0603]  349.92 16.25 270 top
CA19  4.7U_0603_6.3V6K  [C_0603]  351.19 18.44 180 top
CA20  1U_0603_10V6K  [C_0603]  350.11 23.46 270 top
CA22  10U_0603_6.3V6M  [C_0603]  348.97 24.92 180 top
CA23  10U_0402_6.3V6M  [C_0402]  344.72 16.92 0 bottom
CA24  0.1U_0402_10V6K  [C_0402]  341.94 15.59 180 top
CA25  4.7U_0603_6.3V6K  [C_0603]  338.8 14.86 180 top
CA26  0.1U_0402_10V6K  [C_0402]  338.13 24.41 180 top
CA27  4.7U_0603_6.3V6K  [C_0603]  339.01 20.28 180 top
CA28  0.1U_0402_10V6K  [C_0402]  338.57 18.19 180 top
CA29  0.1U_0402_10V6K  [C_0402]  342.81 12.72 90 top
CA30  47P_0402_50V8J  [C_0402]  336.35 21.43 180 top
CA36  1000P_0402_50V7K  [C_0402]  323.55 19.36 270 top
CA37  1000P_0402_50V7K  [C_0402]  323.55 16.66 90 top
CA38  1000P_0402_50V7K  [C_0402]  323.55 23.67 270 top
CA39  1000P_0402_50V7K  [C_0402]  323.55 20.98 90 top
CA40  100P_0402_50V8J  [C_0402]  354.74 9.48 90 top
CA41  100P_0402_50V8J  [C_0402]  355.25 12.89 270 top
CA42  680P_0402_50V7K  [C_0402]  363.45 15.65 270 bottom
CA43  680P_0402_50V7K  [C_0402]  367.55 14.05 180 bottom
CA60  33P_0402_50V8J  [C_0402]  355.65 9.48 90 top
CA61  33P_0402_50V8J  [C_0402]  356.19 12.89 270 top
CA62  10P_0402_25V8J  [C_0402]  338.13 23.4 180 top
CA63  10U_0603_6.3V6M  [C_0603]  350.05 24.92 90 top
CA64  10U_0603_6.3V6M~D  [C_0603]  349.43 13.76 0 top
CA65  10U_0603_6.3V6M~D  [C_0603]  347.57 9.36 0 top
CA66  10P_0402_25V8J  [C_0402]  338.57 17.24 180 bottom
CC4  12P_0402_50V8J  [C_0402]  290.06 21.43 180 bottom
CC27  1U_0402_6.3V6K  [C_0402]  266.09 16.22 0 bottom
CC298  0.1U_0402_16V7K  [C_0402]  178.86 77.93 90 top
CD1  1U_0402_6.3V6K  [C_0402]  130.22 42.22 180 top
CD2  1U_0402_6.3V6K  [C_0402]  110.26 43.91 0 top
CD3  1U_0402_6.3V6K  [C_0402]  171.81 43.61 0 top
CD4  1U_0402_6.3V6K  [C_0402]  171.81 42.72 0 top
CD5  10U_0603_6.3V6M  [C_0603]  164.89 42.95 180 top
CD6  10U_0603_6.3V6M  [C_0603]  152.88 43.78 0 top
CD7  10U_0603_6.3V6M  [C_0603]  110.34 42.83 0 top
CD8  10U_0603_6.3V6M  [C_0603]  120.94 43.27 0 top
CD9  10U_0603_6.3V6M  [C_0603]  170.85 42.76 180 top
CD10  10U_0603_6.3V6M  [C_0603]  170.92 44.67 180 top
CD12  1U_0402_6.3V6K  [C_0402]  169.83 34.57 0 top
CD13  10U_0603_6.3V6M  [C_0603]  168.56 34.41 180 top
CD14  10U_0603_6.3V6M  [C_0603]  168.56 35.68 180 top
CD15  10U_0603_6.3V6M  [C_0603]  169.52 35.72 0 top
CD16  0.1U_0402_10V6K  [C_0402]  168.39 44.29 90 top
CD17  2.2U_0402_6.3V6M  [C_0402]  167.51 44.29 90 top
CD19  1U_0402_6.3V6K  [C_0402]  203.12 35.21 180 top
CD20  1U_0402_6.3V6K  [C_0402]  192.46 34.19 180 top
CD21  1U_0402_6.3V6K  [C_0402]  229.99 43.46 180 top
CD22  1U_0402_6.3V6K  [C_0402]  214.02 35.14 0 top
CD23  10U_0603_6.3V6M  [C_0603]  230.93 43.27 0 top
CD24  10U_0603_6.3V6M  [C_0603]  240.89 43.4 180 top
CD25  10U_0603_6.3V6M  [C_0603]  225.85 35.27 0 top
CD26  10U_0603_6.3V6M  [C_0603]  198.03 43.14 180 top
CD27  10U_0603_6.3V6M  [C_0603]  246.99 42.19 180 top
CD28  10U_0603_6.3V6M  [C_0603]  246.99 43.4 180 top
CD29  0.1U_0402_10V6K  [C_0402]  223.07 34.19 90 top
CD30  1U_0402_6.3V6K  [C_0402]  246.75 41.05 180 top
CD31  1U_0402_6.3V6K  [C_0402]  246.75 40.16 180 top
CD32  1U_0402_6.3V6K  [C_0402]  245.68 35.84 180 top
CD33  330U_2.5V_M  [C_APXK2R5ARA331MF451]  183.26 29.99 90 bottom
CD34  0.1U_0402_10V6K  [C_0402]  243.37 42.37 90 top
CD35  2.2U_0402_6.3V6M  [C_0402]  244.39 42.37 90 top
CD36  4.7U_0603_6.3V6K  [C_0603]  281.41 20.48 270 top
CD37  0.22U_0402_10V6K  [C_0402]  269.65 23.85 0 bottom
CD38  0.1U_0402_10V6K  [C_0402]  284.02 8.52 0 bottom
CD39  0.01U_0402_16V7K  [C_0402]  281.5 21.95 90 top
CD40  47P_0402_50V8J  [C_0402]  284.02 7.57 0 bottom
CD41  15P_0402_50V8J  [C_0402]  282.42 21.99 90 top
CD42  0.22U_0402_10V6K  [C_0402]  269.65 22.97 0 bottom
CD43  0.22U_0402_10V6K  [C_0402]  269.65 20.73 0 bottom
CD44  0.22U_0402_10V6K  [C_0402]  269.65 19.84 0 bottom
CD45  0.22U_0402_10V6K  [C_0402]  269.65 17.31 0 bottom
CD46  0.22U_0402_10V6K  [C_0402]  269.65 16.42 0 bottom
CD51  0.22U_0402_10V6K  [C_0402]  269.65 13.57 0 bottom
CD53  0.22U_0402_10V6K  [C_0402]  269.65 14.46 0 bottom
CD69  .1U_0402_16V7K  [C_0402]  202.86 30.88 90 bottom
CD70  10U_0603_6.3V6M  [C_0603]  142.66 42.7 0 top
CD71  10U_0603_6.3V6M  [C_0603]  116.75 35.27 180 top
CD72  10U_0603_6.3V6M  [C_0603]  149.45 35.4 180 top
CD73  10U_0603_6.3V6M  [C_0603]  130.36 43.35 180 top
CD74  1U_0402_6.3V6K  [C_0402]  105.59 35.27 180 top
CD75  1U_0402_6.3V6K  [C_0402]  144.39 35.27 180 top
CD76  1U_0402_6.3V6K  [C_0402]  126.67 35.27 180 top
CD77  1U_0402_6.3V6K  [C_0402]  153.43 42.67 0 top
CD78  1U_0402_6.3V6K  [C_0402]  159.42 35.22 270 top
CD79  1U_0402_6.3V6K  [C_0402]  164.9 44.03 180 top
CD80  1U_0402_6.3V6K  [C_0402]  208.59 35.21 180 top
CD81  1U_0402_6.3V6K  [C_0402]  236.31 34.19 0 top
CD82  1U_0402_6.3V6K  [C_0402]  225.45 34.19 0 top
CD83  1U_0402_6.3V6K  [C_0402]  181.92 34 180 top
CD84  10U_0603_6.3V6M  [C_0603]  222.99 43.53 0 top
CD85  10U_0603_6.3V6M  [C_0603]  214.16 43.14 180 top
CD86  10U_0603_6.3V6M  [C_0603]  187.36 43.46 0 top
CD87  10U_0603_6.3V6M  [C_0603]  182.16 35.14 180 top
CD88  10U_0603_6.3V6M  [C_0603]  246.89 35.98 0 top
CD89  10U_0603_6.3V6M  [C_0603]  246.89 34.71 0 top
CD90  10U_0603_6.3V6M  [C_0603]  245.86 34.71 180 top
CD96  0.1U_0402_10V6K  [C_0402]  145.45 34.37 90 top
CD97  .1U_0402_16V7K  [C_0402]  206.11 35.21 180 top
CE1  0.1U_0402_10V7K~D  [C_0402]  118.47 25.06 270 bottom
CE2  0.1U_0402_10V6K  [C_0402]  128.93 28.6 0 bottom
CE4  1U_0402_6.3V6K  [C_0402]  194.12 30.76 90 bottom
CE5  1U_0402_6.3V6K  [C_0402]  201.04 31.75 0 bottom
CE6  10U_0603_6.3V6M~D  [C_0603]  195.23 30.72 90 bottom
CE8  0.047U_0402_16V4Z  [C_0402]  320.5 20.26 0 top
CE9  22P_0402_50V8J  [C_0402]  157.39 28.97 90 bottom
CE10  22P_0402_50V8J  [C_0402]  155.49 28.97 90 bottom
CE12  2.2U_0402_6.3V6M  [C_0402]  301.49 20.92 180 bottom
CE17  10P_0402_25V8J  [C_0402]  216.83 142.85 270 top
CE18  .1U_0402_16V7K  [C_0402]  262.42 30.58 270 top
CE62  0.1U_0402_10V6K  [C_0402]  317.59 16.79 0 top
CE63  1000P_0402_50V7K  [C_0402]  311.44 23.47 270 bottom
CE64  1000P_0402_50V7K  [C_0402]  314.22 8.41 0 bottom
CE65  0.1U_0402_10V6K  [C_0402]  299.75 12.93 270 bottom
CE66  0.1U_0402_10V6K  [C_0402]  305.09 20.93 270 bottom
CE67  0.1U_0402_10V6K  [C_0402]  304.72 7.97 180 bottom
CE68  0.1U_0402_10V6K  [C_0402]  315.13 9.52 180 bottom
CE69  0.1U_0402_10V6K  [C_0402]  299.7 20.02 90 bottom
CE71  0.1U_0402_10V6K  [C_0402]  308.66 7.97 180 bottom
CE73  0.1U_0402_10V6K  [C_0402]  305.09 25.92 90 bottom
CE76  100P_0402_50V8J  [C_0402]  295.53 10.67 0 top
CE77  0.1U_0402_10V6K  [C_0402]  315.41 20.89 180 bottom
CE79  0.1U_0402_10V6K  [C_0402]  299.75 14.27 90 bottom
CE80  270P_0402_50V7K  [C_0402]  155.49 22.94 90 bottom
CE81  0.1U_0402_10V6K  [C_0402]  307.61 28.07 180 top
CE82  1000P_0402_50V7K  [C_0402]  318.25 11.97 180 top
CE84  100P_0402_50V8J  [C_0402]  298.74 21.03 90 bottom
CE85  0.1U_0402_10V6K  [C_0402]  312.7 28.48 0 top
CE86  47P_0402_50V8J  [C_0402]  315.13 28.04 270 top
CE87  2200P_0402_25V7K  [C_0402]  307.2 26.85 270 bottom
CE89  10U_0603_6.3V6M  [C_0603]  320.14 15.71 0 top
CE91  0.1U_0402_10V6K  [C_0402]  302.03 12.79 0 bottom
CE98  0.1U_0402_10V6K  [C_0402]  307.84 25.87 180 top
CE99  0.01U_0402_16V7K  [C_0402]  102.45 61.55 90 top
CE100  0.01U_0402_16V7K  [C_0402]  308.59 51.62 180 top
CE101  12P_0402_50V8J  [C_0402]  301.41 26.48 180 top
CE102  12P_0402_50V8J  [C_0402]  302.4 26.48 0 top
CE103  1U_0603_25V6K  [C_0603]  293.59 16.56 90 top
CE104  0.1U_0402_10V6K  [C_0402]  306.76 23.38 0 bottom
CE105  270P_0402_50V7K  [C_0402]  157.28 23.84 180 bottom
CE107  2200P_0402_25V7K  [C_0402]  305.98 25.92 90 bottom
CG25  0.22U_0201_6.3V  [C_0201]  195.65 96.23 0 top
CG26  0.22U_0201_6.3V  [C_0201]  197.3 96.54 0 top
CG27  0.22U_0201_6.3V  [C_0201]  197.3 97.12 0 top
CG28  0.22U_0201_6.3V  [C_0201]  196.22 97.69 0 top
CG29  0.22U_0201_6.3V  [C_0201]  196.22 98.26 0 top
CG30  0.22U_0201_6.3V  [C_0201]  198.38 98.58 0 top
CG31  0.22U_0201_6.3V  [C_0201]  198.39 99.15 0 top
CG32  0.22U_0201_6.3V  [C_0201]  196.99 99.47 0 top
CG33  0.22U_0201_6.3V  [C_0201]  196.99 100.04 0 top
CG34  0.1U_0201_6.3V6K  [C_0201]  208.84 100.16 90 top
CG35  0.22U_0201_6.3V  [C_0201]  198.26 100.48 0 top
CG36  0.22U_0201_6.3V  [C_0201]  198.26 101.05 0 top
CG40  0.1U_0402_10V7K  [C_0402]  208.52 93.83 270 top
CG42  4.7U_0603_6.3V6M  [C_0603]  196.64 83.09 0 top
CG43  4.7U_0603_6.3V6M  [C_0603]  202.29 94.64 270 top
CG47  0.1U_0402_10V7K  [C_0402]  202.48 91.39 90 top
CG48  0.1U_0402_10V7K  [C_0402]  205.91 95.54 270 top
CG51  0.1U_0402_10V7K  [C_0402]  208.52 90.21 270 top
CG53  0.1U_0402_10V7K  [C_0402]  206.54 89.12 0 top
CG54  0.1U_0402_16V7K  [C_0402]  212.76 106.58 0 top
CG55  22U_0805_6.3V6M  [C_0805]  215.72 80.29 0 top
CG56  0.1U_0402_16V4Z~D  [C_0402]  227.62 104.73 90 top
CG57  0.1U_0402_16V4Z~D  [C_0402]  227.64 90.45 180 top
CG58  0.1U_0402_16V4Z~D  [C_0402]  223.06 87.6 0 top
CG59  0.1U_0402_10V7K  [C_0402]  219 107.42 270 top
CG60  0.1U_0402_10V7K  [C_0402]  228.21 99.66 180 top
CG61  100P_0402_50V8J~D  [C_0402]  223.88 70.95 0 bottom
CG62  10U_0603_25V6M  [C_0603]  229.85 74.89 90 bottom
CG63  10U_0603_25V6M  [C_0603]  229.85 71.91 90 bottom
CG64  220P_0402_50V8J  [C_0402]  216.65 74.92 90 bottom
CG65  220P_0402_50V8J  [C_0402]  215.74 74.92 90 bottom
CG66  0.1U_0402_16V4Z~D  [C_0402]  188.32 82.95 90 bottom
CG75  22P_0402_50V8J  [C_0402]  196.71 85.7 270 bottom
CG76  22P_0402_50V8J  [C_0402]  196.71 83.01 90 bottom
CG78  820P_0402_25V7  [C_0402]  214.7 135.22 270 bottom
CG79  820P_0402_25V7  [C_0402]  215.62 135.22 270 bottom
CG80  22U_0603_6.3V6M  [C_0603]  232.13 138.05 90 bottom
CG81  22U_0603_6.3V6M  [C_0603]  216.13 131.94 270 bottom
CG82  22U_0603_6.3V6M  [C_0603]  232.13 140.91 90 bottom
CG83  10U_0402_6.3V4Z  [C_0402]  224.2 142.77 180 top
CG84  10U_0402_6.3V4Z  [C_0402]  225.08 141.36 90 top
CG85  10U_0402_6.3V4Z  [C_0402]  225 129.06 0 top
CG86  1U_0402_6.3V4Z  [C_0402]  223.3 139.1 270 top
CG87  1U_0402_6.3V4Z  [C_0402]  223.3 141.01 270 top
CG88  1U_0402_6.3V4Z  [C_0402]  222.48 131.74 270 top
CG89  1U_0402_6.3V4Z  [C_0402]  222.48 132.92 90 top
CG90  1U_0402_6.3V4Z  [C_0402]  225.54 130.91 270 top
CG91  1U_0402_6.3V4Z  [C_0402]  225.84 133.17 90 top
CG97  22U_0603_6.3V6M  [C_0603]  213.46 133.27 270 bottom
CG98  22U_0603_6.3V6M  [C_0603]  213.46 130.35 270 bottom
CG99  22U_0603_6.3V6M  [C_0603]  213.4 141.7 270 bottom
CG100  10U_0402_6.3V4Z  [C_0402]  203.87 131.17 270 top
CG101  10U_0402_6.3V4Z  [C_0402]  204.86 140.97 270 top
CG102  10U_0402_6.3V4Z  [C_0402]  212 140.23 90 top
CG103  1U_0402_6.3V4Z  [C_0402]  241.47 130.18 270 top
CG104  1U_0402_6.3V4Z  [C_0402]  206.41 139.23 270 top
CG105  1U_0402_6.3V4Z  [C_0402]  203.74 133.11 90 top
CG106  1U_0402_6.3V4Z  [C_0402]  199.17 133.07 270 top
CG113  820P_0402_25V7  [C_0402]  258.38 122.33 180 bottom
CG114  820P_0402_25V7  [C_0402]  258.38 123.21 180 bottom
CG115  22U_0603_6.3V6M  [C_0603]  264.12 122.77 0 bottom
CG116  22U_0603_6.3V6M  [C_0603]  261.26 122.77 0 bottom
CG117  22U_0603_6.3V6M  [C_0603]  255.47 122.77 180 bottom
CG118  10U_0402_6.3V4Z  [C_0402]  261.46 121.94 0 top
CG119  10U_0402_6.3V4Z  [C_0402]  259.05 92.48 0 top
CG120  10U_0402_6.3V4Z  [C_0402]  261.48 121.06 0 top
CG121  1U_0402_6.3V4Z  [C_0402]  257.98 112.36 180 top
CG122  1U_0402_6.3V4Z  [C_0402]  258.86 112.36 0 top
CG123  1U_0402_6.3V4Z  [C_0402]  263.12 108.42 180 top
CG124  1U_0402_6.3V4Z  [C_0402]  261.54 115.28 0 top
CG125  1U_0402_6.3V4Z  [C_0402]  258.87 113.31 0 top
CG126  1U_0402_6.3V4Z  [C_0402]  256.7 101.12 0 top
CG132  22U_0603_6.3V6M  [C_0603]  248.13 138.43 90 bottom
CG133  22U_0603_6.3V6M  [C_0603]  248.13 141.54 90 bottom
CG134  22U_0603_6.3V6M  [C_0603]  247.88 129.63 270 bottom
CG135  10U_0402_6.3V4Z  [C_0402]  240.84 139.34 180 top
CG136  10U_0402_6.3V4Z  [C_0402]  239.37 141.12 90 top
CG137  10U_0402_6.3V4Z  [C_0402]  240.89 141.12 90 top
CG138  1U_0402_6.3V4Z  [C_0402]  238.67 133.71 270 top
CG139  1U_0402_6.3V4Z  [C_0402]  237.89 139.52 0 top
CG140  1U_0402_6.3V4Z  [C_0402]  239.93 138.39 0 top
CG141  1U_0402_6.3V4Z  [C_0402]  238.87 135.47 180 top
CG148  820P_0402_25V7  [C_0402]  256.38 90.26 0 bottom
CG149  820P_0402_25V7  [C_0402]  256.38 88.48 0 bottom
CG150  22U_0603_6.3V6M  [C_0603]  261.9 87.65 0 bottom
CG151  22U_0603_6.3V6M  [C_0603]  250.24 87.65 180 bottom
CG152  22U_0603_6.3V6M  [C_0603]  258.91 87.65 0 bottom
CG153  10U_0402_6.3V4Z  [C_0402]  261.59 78.96 0 top
CG154  10U_0402_6.3V4Z  [C_0402]  261.53 87.78 0 top
CG155  10U_0402_6.3V4Z  [C_0402]  257.6 82.32 90 top
CG156  1U_0402_6.3V4Z  [C_0402]  256.83 77.43 0 top
CG157  1U_0402_6.3V4Z  [C_0402]  262.8 90.77 0 top
CG158  1U_0402_6.3V4Z  [C_0402]  264 83.21 0 top
CG159  1U_0402_6.3V4Z  [C_0402]  264 84.1 0 top
CG160  1U_0402_6.3V4Z  [C_0402]  264.66 87.08 180 top
CG161  1U_0402_6.3V4Z  [C_0402]  260.82 89.56 0 top
CG167  22U_0603_6.3V6M  [C_0603]  262.4 106.77 0 bottom
CG168  22U_0603_6.3V6M  [C_0603]  261.64 90.77 0 bottom
CG169  22U_0603_6.3V6M  [C_0603]  253.29 91.02 180 bottom
CG170  10U_0402_6.3V4Z  [C_0402]  259.08 97.94 180 top
CG171  10U_0402_6.3V4Z  [C_0402]  262.61 92.48 0 top
CG172  10U_0402_6.3V4Z  [C_0402]  256.57 96.54 0 top
CG173  1U_0402_6.3V4Z  [C_0402]  260.35 98.83 180 top
CG174  1U_0402_6.3V4Z  [C_0402]  255.76 100.22 90 top
CG175  1U_0402_6.3V4Z  [C_0402]  257.54 95.67 270 top
CG176  1U_0402_6.3V4Z  [C_0402]  260.83 92.48 0 top
CG184  10U_0603_6.3V6M  [C_0603]  233.97 88.74 0 top
CG185  10U_0603_6.3V6M  [C_0603]  233.91 91.02 0 top
CG186  10U_0603_6.3V6M  [C_0603]  233.91 95.09 0 top
CG187  10U_0603_6.3V6M  [C_0603]  233.55 97.39 0 top
CG188  10U_0603_6.3V6M  [C_0603]  233.97 99.34 0 top
CG189  10U_0603_6.3V6M  [C_0603]  233.53 101.56 0 top
CG190  10U_0603_6.3V6M  [C_0603]  233.97 107.53 0 top
CG191  10U_0603_6.3V6M  [C_0603]  233.97 109.88 0 top
CG192  1U_0402_6.3V4Z  [C_0402]  227.95 96.23 180 top
CG193  1U_0402_6.3V4Z  [C_0402]  228.02 103.09 180 top
CG194  1U_0402_6.3V4Z  [C_0402]  227.76 107.42 270 top
CG195  1U_0402_6.3V4Z  [C_0402]  226.87 107.42 270 top
CG196  1U_0402_6.3V4Z  [C_0402]  223.25 107.42 270 top
CG197  1U_0402_6.3V4Z  [C_0402]  213.72 108.42 270 top
CG198  1U_0402_6.3V4Z  [C_0402]  222.1 86.63 90 top
CG199  1U_0402_6.3V4Z  [C_0402]  211.57 108.37 270 top
CG200  1U_0402_6.3V4Z  [C_0402]  215.82 107.42 270 top
CG201  1U_0402_6.3V4Z  [C_0402]  216.71 107.42 270 top
CG202  1U_0402_6.3V4Z  [C_0402]  214.93 107.42 270 top
CG203  1U_0402_6.3V4Z  [C_0402]  220.58 107.4 270 top
CG204  1U_0402_6.3V4Z  [C_0402]  221.45 107.28 0 top
CG205  1U_0402_6.3V4Z  [C_0402]  227.77 94.83 180 top
CG206  1U_0402_6.3V4Z  [C_0402]  224.14 107.42 270 top
CG207  1U_0402_6.3V4Z  [C_0402]  227.64 91.97 180 top
CG208  1U_0402_6.3V4Z  [C_0402]  227.64 88.48 180 top
CG209  1U_0402_6.3V4Z  [C_0402]  227.57 87.53 180 top
CG210  1U_0402_6.3V4Z  [C_0402]  220.01 87.53 90 top
CG211  1U_0402_6.3V4Z  [C_0402]  227.96 89.37 180 top
CG212  1U_0402_6.3V4Z  [C_0402]  217.85 107.42 270 top
CG213  1U_0402_6.3V4Z  [C_0402]  215.82 87.4 90 top
CG214  1U_0402_6.3V4Z  [C_0402]  224.9 87.58 90 top
CG215  1U_0402_6.3V4Z  [C_0402]  225.79 87.58 90 top
CG216  10U_0603_6.3V6M  [C_0603]  222.05 84.23 270 top
CG217  10U_0603_6.3V6M  [C_0603]  228.45 86.39 0 top
CG218  10U_0603_6.3V6M  [C_0603]  230.1 84.28 270 top
CG219  10U_0603_6.3V6M  [C_0603]  233.91 103.53 0 top
CG220  22U_0603_6.3V6M  [C_0603]  233.91 92.93 0 top
CG221  22U_0603_6.3V6M  [C_0603]  229.54 78.96 90 top
CG222  22U_0603_6.3V6M  [C_0603]  219.97 84.23 270 top
CG223  22U_0603_6.3V6M  [C_0603]  233.97 111.69 0 top
CG224  22U_0603_6.3V6M  [C_0603]  226.33 84.99 270 top
CG225  22U_0603_6.3V6M  [C_0603]  234.54 80.04 270 top
CG226  22U_0603_6.3V6M  [C_0603]  231.63 77.56 90 top
CG227  22U_0603_6.3V6M  [C_0603]  233.25 77.94 90 top
CG228  22U_0603_6.3V6M  [C_0603]  218.28 84.23 270 top
CG230  0.1U_0402_10V7K  [C_0402]  206.8 87.03 270 top
CG231  10U_0603_6.3V6M  [C_0603]  208.07 76.35 270 bottom
CG232  47U_0805_6.3V6M~D  [C_0805]  209.6 76.5 270 bottom
CG233  0.1U_0402_10V7K  [C_0402]  207.81 95.47 315 top
CG234  0.1U_0402_10V7K  [C_0402]  218.92 87.58 90 top
CG235  0.1U_0402_10V7K  [C_0402]  205.91 87.03 270 top
CG236  0.1U_0402_10V7K  [C_0402]  203.86 86.84 90 top
CG237  0.1U_0402_10V7K  [C_0402]  225.35 107.42 270 top
CG238  0.1U_0402_10V7K  [C_0402]  202.97 86.84 90 top
CG239  22U_0805_6.3VAM  [C_0805]  200.54 85.75 180 top
CG240  0.01U_0402_16V  [C_0402]  213.47 79.08 0 top
CG242  220U_D2 SX_2VY_R9M  [C_D2E]  260.32 129.95 0 bottom
CG243  10U_0603_6.3V6M  [C_0603]  233.97 86.87 0 top
CG244  470U_D2_2VM_R4.5M~D  [C_D1]  210.69 101.5 0 top
CG245  10U_0603_6.3V6M  [C_0603]  198.29 110.82 270 top
CG246  0.1U_0201_6.3V6K  [C_0201]  220.97 61.68 0 top
CG288  22U_0603_6.3V6M  [C_0603]  218.54 72.16 0 bottom
CG289  10U_0603_6.3V6M  [C_0603]  213.91 70.7 90 bottom
CG290  10U_0603_6.3V6M  [C_0603]  214.16 74.39 90 bottom
CG291  4.7U_0402_6.3V6M  [C_0402]  207.56 84.55 270 top
CG292  1U_0402_6.3V4Z  [C_0402]  206.07 85.25 270 top
CG293  0.1U_0201_6.3V6K  [C_0201]  207.59 87.08 0 top
CG294  0.1U_0201_6.3V6K  [C_0201]  205.89 88.36 225 top
CG295  4.7U_0402_6.3V6M  [C_0402]  215.11 83.34 0 top
CG296  4.7U_0402_6.3V6M  [C_0402]  206.44 99.59 180 top
CG297  4.7U_0402_6.3V6M  [C_0402]  211.49 83.81 0 top
CG298  1U_0402_6.3V4Z  [C_0402]  215.11 85.11 0 top
CG299  1U_0402_6.3V4Z  [C_0402]  215.11 84.23 0 top
CG300  1U_0402_6.3V4Z  [C_0402]  211.49 84.7 0 top
CG301  0.1U_0201_6.3V6K  [C_0201]  199.29 91.27 180 top
CG302  0.1U_0201_6.3V6K  [C_0201]  208.8 96.82 270 top
CG303  0.1U_0201_6.3V6K  [C_0201]  211.48 87.59 180 top
CG304  0.1U_0201_6.3V6K  [C_0201]  208.23 96.82 270 top
CG305  0.1U_0201_6.3V6K  [C_0201]  199.29 90.7 180 top
CG306  0.1U_0201_6.3V6K  [C_0201]  206.46 96.29 180 top
CG307  0.1U_0201_6.3V6K  [C_0201]  212.71 87.93 90 top
CG308  0.1U_0402_10V7K  [C_0402]  197.71 90.19 90 top
CG309  0.1U_0402_10V7K  [C_0402]  196.75 90.19 90 top
CG310  1U_0402_6.3V6K  [C_0402]  195.8 90.19 90 top
CG311  4.7U_0603_6.3V6M  [C_0603]  196.64 84.29 0 top
CG313  0.01U_0402_16V7K  [C_0402]  216.13 134.9 0 top
CG314  0.01U_0402_16V7K  [C_0402]  213.71 132.17 180 top
CG315  0.01U_0402_16V7K  [C_0402]  258.81 122.58 0 top
CG316  0.01U_0402_16V7K  [C_0402]  248.83 134.96 180 bottom
CG317  0.01U_0402_16V7K  [C_0402]  258.43 87.97 270 top
CG318  0.01U_0402_16V7K  [C_0402]  254.29 91.14 90 top
CG320  10U_0603_6.3V6M  [C_0603]  217.79 74.38 90 bottom
CG322  1U_0402_6.3V6K  [C_0402]  207.81 64.6 90 top
CG323  1U_0402_6.3V6K~D  [C_0402]  209.23 58.74 0 top
CG324  22U_0603_6.3V6M  [C_0603]  253.29 89.69 180 bottom
CG325  10U_0402_6.3V4Z  [C_0402]  239.62 130.7 90 top
CG326  10U_0402_6.3V4Z  [C_0402]  260.83 90.58 0 top
CG327  10U_0402_6.3V4Z  [C_0402]  211.88 130.03 270 top
CG328  1U_0402_6.3V4Z  [C_0402]  203.18 142.96 180 top
CG329  1U_0402_6.3V4Z  [C_0402]  205.28 142.65 180 top
CG330  1U_0402_6.3V4Z  [C_0402]  206.85 133.9 270 top
CG331  1U_0402_6.3V4Z  [C_0402]  203.73 135.91 0 top
CG332  1U_0402_6.3V4Z  [C_0402]  203.73 135.03 0 top
CG333  1U_0402_6.3V4Z  [C_0402]  241.65 133.71 270 top
CG334  1U_0402_6.3V4Z  [C_0402]  264.4 91.83 90 top
CG335  1U_0402_6.3V4Z  [C_0402]  265.24 77.94 180 top
CG336  1U_0402_6.3V4Z  [C_0402]  206.12 141.28 270 top
CG337  1U_0402_6.3V4Z  [C_0402]  239.87 135.84 90 top
CG338  1U_0402_6.3V4Z  [C_0402]  238.87 134.58 180 top
CG339  1U_0402_6.3V4Z  [C_0402]  260.83 91.53 0 top
CG340  1U_0402_6.3V4Z  [C_0402]  238.67 130.7 90 top
CG341  1U_0402_6.3V4Z  [C_0402]  205.77 130.25 90 top
CG342  1U_0402_6.3V4Z  [C_0402]  239.56 129.71 270 top
CG343  1U_0402_6.3V4Z  [C_0402]  263.06 98.88 90 top
CG344  22U_0603_6.3V6M  [C_0603]  265.47 94.07 90 top
CG345  10U_0402_6.3V4Z  [C_0402]  240.84 140.23 180 top
CG346  10U_0402_6.3V4Z  [C_0402]  204.7 133.11 90 top
CG347  10U_0402_6.3V4Z  [C_0402]  260.28 106.01 180 top
CG348  1U_0402_6.3V4Z  [C_0402]  206.92 131.08 90 top
CG349  1U_0402_6.3V4Z  [C_0402]  264.14 94.59 270 top
CG350  1U_0402_6.3V4Z  [C_0402]  224.19 138.25 90 top
CG351  1U_0402_6.3V4Z  [C_0402]  259.18 80.29 0 top
CG352  1U_0402_6.3V4Z  [C_0402]  241.47 131.02 90 top
CG353  1U_0402_6.3V4Z  [C_0402]  204.82 130.25 90 top
CG354  1U_0402_6.3V4Z  [C_0402]  259.64 126.15 270 top
CG355  1U_0402_6.3V4Z  [C_0402]  240.45 129.71 270 top
CG356  1U_0402_6.3V4Z  [C_0402]  260.85 97.94 180 top
CG357  1U_0402_6.3V4Z  [C_0402]  205.9 133.9 270 top
CG358  1U_0402_6.3V4Z  [C_0402]  238.67 129.7 270 top
CG359  1U_0402_6.3V4Z  [C_0402]  239.8 134.64 0 top
CG360  1U_0402_6.3V4Z  [C_0402]  225.08 138.25 90 top
CG361  1U_0402_6.3V4Z  [C_0402]  265.36 77.05 180 top
CG362  1U_0402_6.3V4Z  [C_0402]  240.57 133.71 270 top
CG363  1U_0402_6.3V4Z  [C_0402]  203.73 136.87 0 top
CG364  22U_0603_6.3V6M  [C_0603]  249.09 129.63 270 bottom
CG365  10U_0402_6.3V4Z  [C_0402]  262.38 124.68 180 top
CG366  10U_0402_6.3V4Z  [C_0402]  261.22 105.93 90 top
CG367  10U_0402_6.3V4Z  [C_0402]  260.28 106.9 180 top
CG368  1U_0402_6.3V4Z  [C_0402]  204.71 132.24 180 top
CG369  1U_0402_6.3V4Z  [C_0402]  208.05 137.12 0 top
CG370  1U_0402_6.3V4Z  [C_0402]  254.03 122.07 0 top
CG371  1U_0402_6.3V4Z  [C_0402]  205.47 138.31 90 top
CG372  1U_0402_6.3V4Z  [C_0402]  240.51 130.7 90 top
CG373  1U_0402_6.3V4Z  [C_0402]  222.46 137.12 0 top
CG374  1U_0402_6.3V4Z  [C_0402]  262.38 123.72 180 top
CG375  1U_0402_6.3V4Z  [C_0402]  206.98 130.15 270 top
CG376  1U_0402_6.3V4Z  [C_0402]  262.38 122.83 180 top
CG377  1U_0402_6.3V4Z  [C_0402]  256.7 100.16 0 top
CG378  1U_0402_6.3V4Z  [C_0402]  262.12 98.83 180 top
CG379  1U_0402_6.3V4Z  [C_0402]  262.8 89.81 0 top
CG380  1U_0402_6.3V4Z  [C_0402]  224.51 136.22 90 top
CG381  1U_0402_6.3V4Z  [C_0402]  260.52 123.52 90 top
CG382  1U_0402_6.3V4Z  [C_0402]  239.62 133.71 270 top
CG383  1U_0402_6.3V4Z  [C_0402]  259.65 99.72 180 top
CG384  0.1U_0402_10V7K  [C_0402]  206.92 64.66 90 top
CG385  10U_0402_6.3V6M  [C_0402]  209.23 59.76 0 top
CG386  0.1U_0402_10V7K  [C_0402]  220.31 70.51 0 bottom
CG388  22U_0603_6.3V6M  [C_0603]  216 129.18 270 bottom
CG389  22U_0603_6.3V6M  [C_0603]  214.86 133.12 0 bottom
CG390  22U_0603_6.3V6M  [C_0603]  216.25 139.47 90 bottom
CG391  10U_0402_6.3V4Z  [C_0402]  223.5 129.82 180 top
CG392  10U_0402_6.3V4Z  [C_0402]  224.63 132.04 0 top
CG393  10U_0402_6.3V4Z  [C_0402]  222.72 134.77 0 top
CG394  1U_0402_6.3V4Z  [C_0402]  224.58 130.91 270 top
CG395  1U_0402_6.3V4Z  [C_0402]  225.14 135.22 0 top
CG396  1U_0402_6.3V4Z  [C_0402]  238.87 136.42 180 top
CG397  1U_0402_6.3V4Z  [C_0402]  223.49 131.74 270 top
CG398  1U_0402_6.3V4Z  [C_0402]  221.14 137.12 180 top
CG399  1U_0402_6.3V4Z  [C_0402]  224.89 133.18 90 top
CG400  1U_0402_6.3V4Z  [C_0402]  223.43 132.87 90 top
CG401  1U_0402_6.3V4Z  [C_0402]  238.81 137.38 180 top
CG402  1U_0402_6.3V4Z  [C_0402]  224.2 141.88 180 top
CG403  1U_0402_6.3V4Z  [C_0402]  224.19 141.01 270 top
CG404  22U_0603_6.3V6M  [C_0603]  252.9 122.77 180 bottom
CG405  22U_0603_6.3V6M  [C_0603]  255.89 108.2 0 top
CG406  22U_0603_6.3V6M  [C_0603]  200.5 144.68 0 bottom
CG407  10U_0402_6.3V4Z  [C_0402]  260.7 99.72 0 top
CG408  10U_0402_6.3V4Z  [C_0402]  260.33 108.43 0 top
CG409  10U_0402_6.3V4Z  [C_0402]  255.82 121.11 90 top
CG410  1U_0402_6.3V4Z  [C_0402]  261.59 114.27 0 top
CG411  1U_0402_6.3V4Z  [C_0402]  257.81 124.57 0 top
CG412  1U_0402_6.3V4Z  [C_0402]  257.81 125.49 0 top
CG413  1U_0402_6.3V4Z  [C_0402]  254.03 121.09 0 top
CG414  1U_0402_6.3V4Z  [C_0402]  262.7 97.94 180 top
CG415  1U_0402_6.3V4Z  [C_0402]  258.57 98.83 180 top
CG416  1U_0402_6.3V4Z  [C_0402]  255.76 113.04 90 top
CG417  1U_0402_6.3V4Z  [C_0402]  255.88 98.89 0 top
CG418  1U_0402_6.3V4Z  [C_0402]  259.55 127.03 0 top
CG419  1U_0402_6.3V4Z  [C_0402]  257.79 123.65 0 top
CG420  22U_0603_6.3V6M  [C_0603]  252.71 87.65 180 bottom
CG421  22U_0603_6.3V6M  [C_0603]  259.44 106.45 0 bottom
CG422  22U_0603_6.3V6M  [C_0603]  197.78 139.79 270 bottom
CG423  10U_0402_6.3V4Z  [C_0402]  263.45 78.83 90 top
CG424  10U_0402_6.3V4Z  [C_0402]  260.65 88.68 270 top
CG425  10U_0402_6.3V4Z  [C_0402]  264.02 82.32 0 top
CG426  1U_0402_6.3V4Z  [C_0402]  261.67 80.8 0 top
CG427  1U_0402_6.3V4Z  [C_0402]  264.66 86.19 180 top
CG428  1U_0402_6.3V4Z  [C_0402]  265.22 78.82 90 top
CG429  1U_0402_6.3V4Z  [C_0402]  261.97 86.19 0 top
CG430  1U_0402_6.3V4Z  [C_0402]  261.67 79.91 0 top
CG431  1U_0402_6.3V4Z  [C_0402]  264.33 78.83 90 top
CG432  1U_0402_6.3V4Z  [C_0402]  260 86.19 0 top
CG433  1U_0402_6.3V4Z  [C_0402]  255.12 83.23 270 top
CG434  1U_0402_6.3V4Z  [C_0402]  264.02 81.37 0 top
CG435  1U_0402_6.3V4Z  [C_0402]  259.19 79.4 0 top
CG438  0.1U_0201_6.3V6K  [C_0201]  208.57 64.51 90 top
CG439  0.1U_0201_6.3V6K  [C_0201]  203.11 64.63 90 top
CG440  0.1U_0201_6.3V6K  [C_0201]  211.96 77.37 0 top
CG442  2200P_0402_25V7K  [C_0402]  227.28 60.86 270 top
CG482  0.047U_0402_16V4Z  [C_0402]  114.87 86.24 180 bottom
CG483  0.1U_0201_6.3V6K  [C_0201]  197.4 70.93 270 bottom
CG487  0.1U_0402_10V7K  [C_0402]  204.26 60.81 270 top
CG488  0.22U_0201_6.3V  [C_0201]  196.98 101.44 0 top
CG489  0.22U_0201_6.3V  [C_0201]  196.98 102.01 0 top
CG490  0.22U_0201_6.3V  [C_0201]  198.31 102.33 0 top
CG491  0.22U_0201_6.3V  [C_0201]  198.31 102.9 0 top
CG492  0.22U_0201_6.3V  [C_0201]  197.11 103.91 0 top
CG493  0.22U_0201_6.3V  [C_0201]  197.11 103.34 0 top
CG494  0.22U_0201_6.3V  [C_0201]  198.31 104.23 0 top
CG495  0.22U_0201_6.3V  [C_0201]  198.33 104.8 0 top
CG496  0.22U_0201_6.3V  [C_0201]  199.52 105.81 0 top
CG497  0.22U_0201_6.3V  [C_0201]  199.52 105.25 0 top
CG498  0.22U_0201_6.3V  [C_0201]  197.99 106.52 0 top
CG499  0.22U_0201_6.3V  [C_0201]  197.99 105.95 0 top
CG500  0.22U_0201_6.3V  [C_0201]  199.52 107.34 0 top
CG501  0.22U_0201_6.3V  [C_0201]  199.52 106.77 0 top
CG502  0.22U_0201_6.3V  [C_0201]  198.31 108.36 0 top
CG503  0.22U_0201_6.3V  [C_0201]  198.31 107.79 0 top
CG504  1U_0402_6.3V6K  [C_0402]  204.73 95.56 270 top
CG505  4.7U_0603_6.3V6M  [C_0603]  210.04 88.23 180 top
CG506  0.22U_0201_6.3V  [C_0201]  196.8 94.26 0 top
CG507  4.7U_0603_6.3V6M  [C_0603]  213.47 88.16 0 top
CG508  22U_0805_6.3V6M  [C_0805]  212.73 73.65 180 bottom
CG509  1U_0402_6.3V6K  [C_0402]  208.51 91.07 90 top
CG510  4.7U_0603_6.3V6M  [C_0603]  199.68 88.61 270 top
CG511  10U_0603_6.3V6M  [C_0603]  200.89 87.21 90 top
CG512  1U_0402_6.3V6K  [C_0402]  209.47 86.4 270 top
CG513  0.22U_0201_6.3V  [C_0201]  196.8 93.69 0 top
CG514  10U_0603_6.3V6M  [C_0603]  212.62 70.74 90 bottom
CG515  10U_0603_6.3V6M  [C_0603]  211.35 70.74 90 bottom
CG516  0.22U_0201_6.3V  [C_0201]  196.8 93.12 0 top
CG517  1U_0402_6.3V6K  [C_0402]  207.93 101.62 0 top
CG518  0.22U_0201_6.3V  [C_0201]  195.65 95.66 0 top
CG519  0.22U_0201_6.3V  [C_0201]  196.8 92.54 0 top
CG520  1U_0402_6.3V6K  [C_0402]  213.72 86.4 270 top
CG521  22U_0805_6.3V6M  [C_0805]  197.02 80.2 90 top
CG522  1U_0402_6.3V6K  [C_0402]  206.47 97.5 180 top
CG523  1U_0402_6.3V6K  [C_0402]  206.68 103.79 180 top
CG524  4.7U_0603_6.3V6M  [C_0603]  203.62 95.34 270 top
CG525  1U_0402_6.3V6K  [C_0402]  208.05 103.03 0 top
CG526  0.1U_0201_6.3V6K  [C_0201]  201.59 75.81 90 bottom
CG527  0.1U_0201_6.3V6K  [C_0201]  117.1 88.5 270 bottom
CG528  330U_D3_2VM_R6M  [C_D3]  220.52 79.5 0 top
CH5  0.22U_0201_6.3V6M  [C_0201]  185.29 102.01 0 bottom
CH6  0.22U_0201_6.3V6M  [C_0201]  185.29 102.58 0 bottom
CH7  0.22U_0201_6.3V6M  [C_0201]  186.61 101.14 0 bottom
CH8  0.22U_0201_6.3V6M  [C_0201]  186.61 101.77 0 bottom
CH9  0.22U_0201_6.3V6M  [C_0201]  185.97 99.93 0 bottom
CH10  0.22U_0201_6.3V6M  [C_0201]  185.97 100.57 0 bottom
CH11  0.22U_0201_6.3V6M  [C_0201]  187.26 98.92 0 bottom
CH12  0.22U_0201_6.3V6M  [C_0201]  187.26 99.55 0 bottom
CH13  0.22U_0201_6.3V6M  [C_0201]  187.26 97.69 0 bottom
CH14  0.22U_0201_6.3V6M  [C_0201]  187.26 98.26 0 bottom
CH15  0.22U_0201_6.3V6M  [C_0201]  188.77 97.39 0 bottom
CH16  0.22U_0201_6.3V6M  [C_0201]  188.77 96.76 0 bottom
CH17  0.22U_0201_6.3V6M  [C_0201]  187.56 95.74 0 bottom
CH18  0.22U_0201_6.3V6M  [C_0201]  187.56 96.38 0 bottom
CH19  0.22U_0201_6.3V6M  [C_0201]  188.89 94.73 0 bottom
CH20  0.22U_0201_6.3V6M  [C_0201]  188.89 95.36 0 bottom
CH21  0.22U_0201_6.3V6M  [C_0201]  188.89 93.9 0 bottom
CH22  0.22U_0201_6.3V6M  [C_0201]  188.89 93.27 0 bottom
CH23  0.22U_0201_6.3V6M  [C_0201]  190.29 92.25 0 bottom
CH24  0.22U_0201_6.3V6M  [C_0201]  190.29 92.88 0 bottom
CH25  0.22U_0201_6.3V6M  [C_0201]  188.77 91.87 0 bottom
CH26  0.22U_0201_6.3V6M  [C_0201]  188.77 91.23 0 bottom
CH27  0.22U_0201_6.3V6M  [C_0201]  190.29 90.34 0 bottom
CH28  0.22U_0201_6.3V6M  [C_0201]  190.29 90.98 0 bottom
CH29  0.22U_0201_6.3V6M  [C_0201]  188.89 89.84 0 bottom
CH30  0.22U_0201_6.3V6M  [C_0201]  188.89 89.2 0 bottom
CH31  0.22U_0201_6.3V6M  [C_0201]  190.42 88.19 0 bottom
CH32  0.22U_0201_6.3V6M  [C_0201]  190.42 88.82 0 bottom
CH33  0.22U_0201_6.3V6M  [C_0201]  189.02 87.17 0 bottom
CH34  0.22U_0201_6.3V6M  [C_0201]  189.02 87.8 0 bottom
CH35  0.22U_0201_6.3V6M  [C_0201]  190.54 86.15 0 bottom
CH36  0.22U_0201_6.3V6M  [C_0201]  190.54 86.79 0 bottom
CH45  8.2P_0402_50V8D  [C_0402]  293.53 26.42 0 bottom
CH46  8.2P_0402_50V8D  [C_0402]  292.67 26.42 180 bottom
CH47  15P_0402_50V8J  [C_0402]  301 51.2 90 bottom
CH48  15P_0402_50V8J  [C_0402]  301 50.34 270 bottom
CH50  10P_0402_25V8J  [C_0402]  299.01 26.51 180 bottom
CH51  10P_0402_25V8J  [C_0402]  293.54 30.81 90 top
CH52  1U_0402_6.3V6K  [C_0402]  292.49 30.74 270 top
CH53  1U_0402_6.3V6K  [C_0402]  292.5 27.42 270 top
CH70  0.1U_0402_10V6K  [C_0402]  283.19 31.16 270 top
CH80  1U_0402_6.3V6K  [C_0402]  286.32 33.43 90 top
CH82  1U_0402_6.3V6K  [C_0402]  289.32 42.58 90 top
CH100  0.022U_0402_16V7K  [C_0402]  220.12 35.12 270 top
CH101  0.022U_0402_16V7K  [C_0402]  111.54 57.37 90 top
CH102  10U_0603_6.3V6M  [C_0603]  175.3 89.47 90 top
CH103  10U_0603_6.3V6M  [C_0603]  175.3 92.14 90 top
CH104  10U_0603_6.3V6M  [C_0603]  175.25 96.1 270 top
CH106  1U_0402_6.3V6K  [C_0402]  183.05 102 90 top
CH110  1U_0402_6.3V6K  [C_0402]  175.3 98.04 270 top
CH111  10U_0603_6.3V6M  [C_0603]  172.36 100.59 270 top
CH112  10U_0603_6.3V6M  [C_0603]  173.85 89.7 180 top
